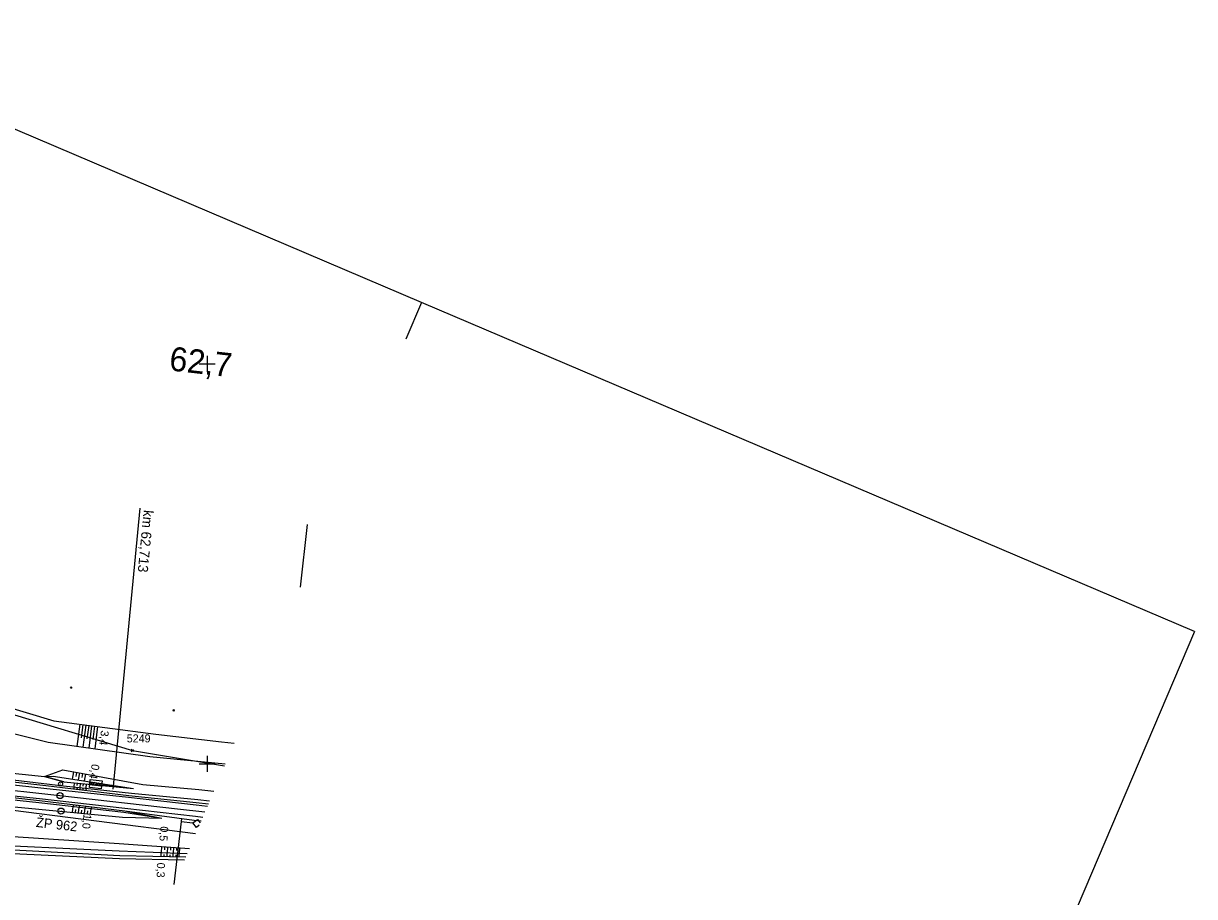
# Model space of a CAD drawing. Extents: x -805636 to -804553, y -1165340 to -1164656.
# Drawn here: x -804845.9 to -804553.1, y -1165133.2 to -1164914.9 of the extents above; entities that cross this region are included whole.
import ezdxf

# ---------------------------------------------------------------- set-up
doc = ezdxf.new("R2010")
doc.units = 0
for name, color, linetype in [('0381KM061-064P - Vrstva 1', 7, 'Continuous'), ('0381KM061-064P - Vrstva 4', 7, 'Continuous'), ('0381KM061-064P - Vrstva 48', 7, 'Continuous'), ('0381KM061-064P - Vrstva 49', 7, 'Continuous'), ('0381KM061-064P - Vrstva 51', 7, 'Continuous'), ('0381KM061-064P - Vrstva 7', 7, 'Continuous'), ('0381KM061-064P - Vrstva 8', 7, 'Continuous'), ('formát', 7, 'Continuous'), ('krizky_1000 - Vrstva 1', 7, 'Continuous'), ('szdc - hran DP', 7, 'Continuous'), ('szdc - szdc_cislo', 7, 'Continuous'), ('szdc - szdc_krizek', 7, 'Continuous'), ('vyt_sit - stávající', 7, 'Continuous')]:
    doc.layers.add(name, color=color, linetype=linetype)

msp = doc.modelspace()

# ---------------------------------------------------------------- linework, layer by layer
at = {"layer": '0381KM061-064P - Vrstva 1'}
msp.add_lwpolyline([(-804885.13, -1165102.52), (-804856.51, -1165105.73), (-804836.78, -1165107.96), (-804807.43, -1165111.28), (-804800.55, -1165112.05)], dxfattribs=at)
at = {"layer": '0381KM061-064P - Vrstva 4'}
for points in [[(-804892.37, -1165100.24), (-804859.84, -1165103.98), (-804840.8, -1165106.06), (-804819.65, -1165108.38), (-804802.7, -1165110.3), (-804799.92, -1165110.56)], [(-804892.28, -1165099.85), (-804859.81, -1165103.25), (-804840.34, -1165105.46), (-804819.52, -1165107.92), (-804802.69, -1165109.64), (-804799.68, -1165110)], [(-804892.24, -1165103.28), (-804860.33, -1165106.74), (-804841.86, -1165108.69), (-804820.53, -1165111.13), (-804802.92, -1165113.13), (-804801.1, -1165113.34)], [(-804892.22, -1165103.81), (-804860.51, -1165107.09), (-804841.9, -1165109.22), (-804820.58, -1165111.74), (-804803.21, -1165114.08), (-804801.49, -1165114.25)]]:
    msp.add_lwpolyline(points, dxfattribs=at)
at = {"layer": '0381KM061-064P - Vrstva 48'}
for p, q in [((-804832.45, -1165095.65), (-804831.74, -1165090.13)), ((-804831.42, -1165093.54), (-804831, -1165090.23)), ((-804830.97, -1165095.86), (-804830.25, -1165090.32)), ((-804829.94, -1165093.74), (-804829.51, -1165090.42)), ((-804829.48, -1165096.06), (-804828.77, -1165090.52)), ((-804828.45, -1165093.95), (-804828.02, -1165090.61)), ((-804827.99, -1165096.27), (-804827.28, -1165090.71)), ((-804833.61, -1165103.81), (-804833.29, -1165102.02)), ((-804832.74, -1165103.22), (-804832.55, -1165102.15)), ((-804832.13, -1165104.04), (-804831.81, -1165102.29)), ((-804831.26, -1165103.46), (-804831.07, -1165102.42)), ((-804830.65, -1165104.27), (-804830.33, -1165102.56)), ((-804833.23, -1165105.8), (-804833.29, -1165106.29)), ((-804833.24, -1165105.79), (-804833.15, -1165104.77)), ((-804832.51, -1165106.08), (-804832.54, -1165106.38)), ((-804832.46, -1165105.46), (-804832.4, -1165104.84)), ((-804831.74, -1165105.96), (-804831.8, -1165106.47)), ((-804831.75, -1165105.96), (-804831.66, -1165104.91)), ((-804831.02, -1165106.25), (-804831.05, -1165106.55)), ((-804830.97, -1165105.61), (-804830.91, -1165104.98)), ((-804830.25, -1165106.12), (-804830.31, -1165106.64)), ((-804830.26, -1165106.12), (-804830.16, -1165105.05)), ((-804833.61, -1165112.12), (-804833.46, -1165110.65)), ((-804833.4, -1165110.23), (-804833.45, -1165110.65)), ((-804832.86, -1165112.2), (-804832.79, -1165111.47)), ((-804832.66, -1165110.31), (-804832.68, -1165110.53)), ((-804832.11, -1165112.27), (-804831.97, -1165110.82)), ((-804831.91, -1165110.4), (-804831.96, -1165110.82)), ((-804831.37, -1165112.34), (-804831.3, -1165111.62)), ((-804831.17, -1165110.49), (-804831.19, -1165110.7)), ((-804830.62, -1165112.41), (-804830.48, -1165111)), ((-804830.42, -1165110.58), (-804830.47, -1165111)), ((-804829.87, -1165112.48), (-804829.81, -1165111.78)), ((-804829.68, -1165110.67), (-804829.7, -1165110.87)), ((-804829.13, -1165112.56), (-804828.99, -1165111.17)), ((-804828.93, -1165110.75), (-804828.98, -1165111.17)), ((-804811.36, -1165120.67), (-804811.46, -1165122.21)), ((-804810.61, -1165120.72), (-804810.66, -1165121.48)), ((-804809.86, -1165120.78), (-804809.96, -1165122.27)), ((-804809.11, -1165120.83), (-804809.16, -1165121.56)), ((-804808.36, -1165120.88), (-804808.46, -1165122.33)), ((-804807.62, -1165120.93), (-804807.67, -1165121.65)), ((-804806.87, -1165120.98), (-804806.97, -1165122.39)), ((-804811.47, -1165123.14), (-804811.45, -1165122.21)), ((-804810.72, -1165123.15), (-804810.71, -1165122.7)), ((-804809.97, -1165123.17), (-804809.95, -1165122.27)), ((-804809.22, -1165123.19), (-804809.21, -1165122.74)), ((-804808.47, -1165123.2), (-804808.45, -1165122.33)), ((-804807.72, -1165123.22), (-804807.71, -1165122.79)), ((-804806.97, -1165123.24), (-804806.95, -1165122.39))]:
    msp.add_line(p, q, dxfattribs=at)
at = {"layer": '0381KM061-064P - Vrstva 49'}
for p, q in [((-804833.78, -1165081.15), (-804834.13, -1165080.8)), ((-804833.78, -1165080.8), (-804834.13, -1165081.15)), ((-804808.18, -1165086.83), (-804808.54, -1165086.48)), ((-804808.18, -1165086.48), (-804808.54, -1165086.83))]:
    msp.add_line(p, q, dxfattribs=at)
for points in [[(-805084.74, -1165039.06), (-805061.55, -1165052.74), (-805034.17, -1165068.7), (-805016.31, -1165078.58), (-804984.31, -1165094.26), (-804952.92, -1165105.84), (-804923.4, -1165113.55), (-804890.69, -1165118.62), (-804860.79, -1165119.97), (-804821.99, -1165121.8), (-804804.98, -1165122.47)], [(-805085.43, -1165039.91), (-805061.8, -1165053.37), (-805034.45, -1165069.27), (-805016.82, -1165079.3), (-804984.87, -1165094.97), (-804952.63, -1165107.29), (-804923.66, -1165115.02), (-804890.91, -1165119.51), (-804860.93, -1165120.87), (-804821.85, -1165122.9), (-804805.33, -1165123.27)], [(-805060.73, -1165049.17), (-805047.98, -1165055.77), (-805031.23, -1165064.28), (-805013.07, -1165072.73), (-804991.62, -1165081.24), (-804976.47, -1165086.37), (-804956.64, -1165091.96), (-804934.05, -1165097.54), (-804913.13, -1165101.06), (-804892.22, -1165103.81), (-804860.51, -1165107.09), (-804841.9, -1165109.22), (-804820.58, -1165111.74), (-804811.31, -1165113.56)], [(-805033.41, -1165066.35), (-805014.98, -1165076.25), (-804982.53, -1165092.31), (-804953.12, -1165104.6), (-804922.96, -1165111.59), (-804890.43, -1165117.32), (-804859.92, -1165117.39), (-804821.94, -1165119.94), (-804804.42, -1165121.15)], [(-805010.72, -1165069.47), (-804990.45, -1165077.48), (-804974.57, -1165082.73), (-804955.28, -1165088.2), (-804932.96, -1165093.51), (-804912.39, -1165097.1), (-804892.28, -1165099.85), (-804859.81, -1165103.25), (-804840.34, -1165105.46), (-804819.52, -1165107.92), (-804802.69, -1165109.64), (-804799.68, -1165110)], [(-804994.86, -1165072.51), (-804973.16, -1165079.86), (-804954.29, -1165084.75), (-804932.5, -1165089.79), (-804920.22, -1165090.5), (-804911.77, -1165084.22), (-804893.29, -1165083.05), (-804876.57, -1165085.04), (-804853.44, -1165091.21), (-804839.72, -1165094.63), (-804814.35, -1165098.18)], [(-804930.03, -1165080.86), (-804917.17, -1165078.41), (-804896.14, -1165076.16), (-804872.64, -1165078.3), (-804857.5, -1165083.55), (-804838.27, -1165089.29), (-804812.85, -1165092.56), (-804796.39, -1165094.52), (-804793.24, -1165094.87)], [(-804892.03, -1165097.79), (-804859.05, -1165101.29), (-804840.64, -1165103.22)], [(-804892.31, -1165098.96), (-804859.08, -1165102.8), (-804835.93, -1165105.5), (-804818.93, -1165107.36), (-804802.32, -1165108.93), (-804799.37, -1165109.27)], [(-804814.35, -1165098.18), (-804795.44, -1165100.05)], [(-804840.64, -1165103.22), (-804836.05, -1165101.51), (-804816.03, -1165105.18), (-804802.02, -1165106.41), (-804798.34, -1165106.84)], [(-804840.64, -1165103.22), (-804838.47, -1165103.07), (-804818.4, -1165106.14)], [(-804840.64, -1165103.22), (-804835.82, -1165104.53), (-804840.64, -1165103.22), (-804835.82, -1165104.53), (-804818.4, -1165106.14)], [(-804892.44, -1165105.41), (-804859.96, -1165109.29), (-804851.61, -1165110.39), (-804821.13, -1165113.33), (-804811.31, -1165113.56)], [(-804892.37, -1165104.14), (-804860.79, -1165107.69), (-804842.05, -1165109.66), (-804820.85, -1165112.11), (-804811.31, -1165113.56)]]:
    msp.add_lwpolyline(points, dxfattribs=at)
at = {"layer": '0381KM061-064P - Vrstva 51'}
msp.add_lwpolyline([(-805085.93, -1165040.55), (-805062.08, -1165054.12), (-805034.69, -1165069.73), (-805017.21, -1165079.65), (-804985.71, -1165095.39), (-804952.66, -1165107.75), (-804923.93, -1165115.31), (-804890.75, -1165120.1), (-804861.18, -1165121.85), (-804821.92, -1165123.67), (-804805.64, -1165124)], dxfattribs=at)
at = {"layer": '0381KM061-064P - Vrstva 7'}
msp.add_line((-804836.67, -1165105.01), (-804836.57, -1165105.03), dxfattribs=at)
for centre, radius in [((-804836.62, -1165105.02), 0.5), ((-804836.78, -1165107.96), 0.75)]:
    msp.add_circle(centre, radius, dxfattribs=at)
at = {"layer": '0381KM061-064P - Vrstva 8'}
for p, q in [((-804823.36, -1165105.59), (-804816.74, -1165036.14)), ((-804776.65, -1165055.87), (-804774.89, -1165040.2)), ((-804829.06, -1165104.6), (-804829.31, -1165104.79)), ((-804828.53, -1165104.66), (-804829.3, -1165105.27)), ((-804828.01, -1165104.72), (-804828.78, -1165105.33)), ((-804827.48, -1165104.77), (-804828.25, -1165105.39)), ((-804826.95, -1165104.83), (-804827.72, -1165105.45)), ((-804826.42, -1165104.89), (-804827.2, -1165105.51)), ((-804826.35, -1165105.31), (-804826.67, -1165105.57)), ((-804823.44, -1165106.34), (-804823.28, -1165104.85)), ((-804806.51, -1165114.46), (-804808.28, -1165130.22)), ((-804806.43, -1165113.71), (-804806.59, -1165115.21))]:
    msp.add_line(p, q, dxfattribs=at)
for points in [[(-804826.45, -1165106.25), (-804829.43, -1165105.91), (-804829.21, -1165103.92), (-804826.23, -1165104.26), (-804826.45, -1165106.25)], [(-804826.34, -1165105.26), (-804823.36, -1165105.59)], [(-804806.51, -1165114.46), (-804803.53, -1165114.8), (-804802.42, -1165113.91), (-804801.72, -1165114.8)], [(-804801.95, -1165115.35), (-804802.65, -1165115.9), (-804803.53, -1165114.8)]]:
    msp.add_lwpolyline(points, dxfattribs=at)
msp.add_lwpolyline([(-804826.38, -1165105.6), (-804829.36, -1165105.26), (-804829.28, -1165104.57), (-804826.3, -1165104.91)], close=True, dxfattribs=at)
at = {"layer": 'formát'}
for p, q in [((-804746.36, -1164984.69), (-804939.6, -1164902.47)), ((-804746.36, -1164984.69), (-804750.28, -1164993.89)), ((-804553.13, -1165066.91), (-804746.36, -1164984.69)), ((-804553.13, -1165066.91), (-804669.4, -1165340.2))]:
    msp.add_line(p, q, dxfattribs=at)
at = {"layer": 'krizky_1000 - Vrstva 1'}
for points in [[(-804800, -1164998), (-804800, -1165002)], [(-804802, -1165000), (-804798, -1165000)], [(-804800, -1165098), (-804800, -1165102)], [(-804802, -1165100), (-804798, -1165100)]]:
    msp.add_lwpolyline(points, dxfattribs=at)
at = {"layer": 'szdc - hran DP'}
for p, q in [((-804851.84, -1165086.69), (-804818.68, -1165096.66)), ((-804818.68, -1165096.66), (-804795.63, -1165100.48)), ((-804802.89, -1165117.55), (-804934.32, -1165100.62))]:
    msp.add_line(p, q, dxfattribs=at)
at = {"layer": 'szdc - szdc_krizek'}
for p, q in [((-804818.42, -1165096.93), (-804818.95, -1165096.4)), ((-804818.95, -1165096.93), (-804818.42, -1165096.4))]:
    msp.add_line(p, q, dxfattribs=at)
at = {"layer": 'vyt_sit - stávající'}
msp.add_line((-804836.57, -1165111.8), (-804836.48, -1165111.85), dxfattribs=at)
msp.add_circle((-804836.52, -1165111.83), 0.756, dxfattribs=at)

# ---------------------------------------------------------------- texts
at = {"layer": '0381KM061-064P - Vrstva 48'}
for s, rotation, p in [('3,4', 262.6656, (-804826.51, -1165091.58)), ('0,4', 259.6289, (-804828.81, -1165099.95)), ('1,0', 264.4873, (-804830.87, -1165112.47)), ('0,5', 266.024, (-804811.67, -1165115.58)), ('0,3', 268.6994, (-804812.52, -1165124.7))]:
    msp.add_text(s, height=2, rotation=rotation, dxfattribs=at).set_placement(p)
at = {"layer": '0381KM061-064P - Vrstva 7'}
msp.add_text('62,7', height=6, rotation=353.5516, dxfattribs=at).set_placement((-804809.66, -1165001.63))
at = {"layer": '0381KM061-064P - Vrstva 8'}
msp.add_text('km 62,713', height=2.5, rotation=264.5581, dxfattribs=at).set_placement((-804815.85, -1165036.49))
at = {"layer": 'szdc - szdc_cislo'}
msp.add_text('5249', height=2, dxfattribs=at).set_placement((-804820.08, -1165094.66))
at = {"layer": 'vyt_sit - stávající'}
msp.add_text('ŽP 962', height=2.4, rotation=353.5611, dxfattribs=at).set_placement((-804842.86, -1165115.77))

doc.saveas('drawing.dxf')
